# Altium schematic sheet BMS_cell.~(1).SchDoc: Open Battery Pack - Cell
size A4; Date: 26/03/2019; Author: Morgane Vallée - Samuel Lesueur; Revision: 1.0; SheetNumber: 3; SheetTotal: 3
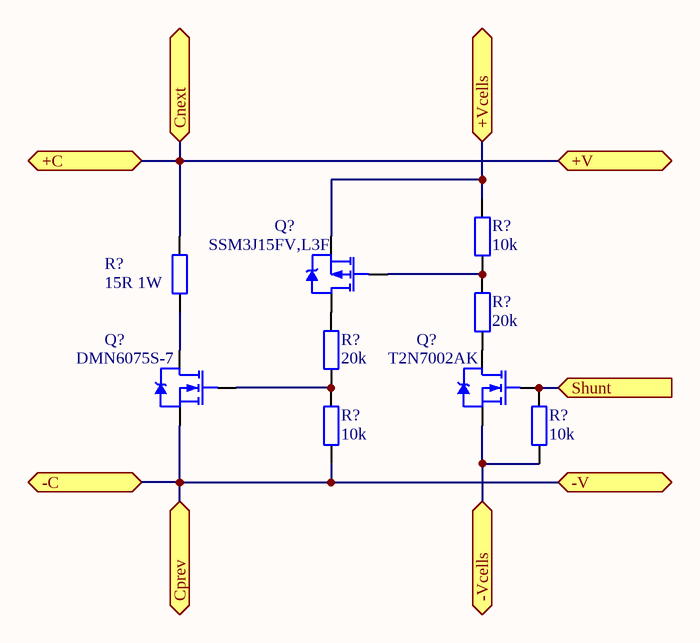
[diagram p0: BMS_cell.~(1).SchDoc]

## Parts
(Parts that share a designator on the sheet are numbered #1, #2 ... from top to bottom, then left to right.)
Q?#1  SSM3J15FV,L3F  [DIODES SOT-23-3]
Q?#2  DMN6075S-7  [DIODES SOT-23-3]
Q?#3  T2N7002AK  [DIODES SOT-23-3]
R?#1  10k  [R0603]
R?#2  15R 1W  [STACKPOLE CSR2512]
R?#3  20k  [R0603]
R?#4  20k  [R0603]
R?#5  10k  [R0603]
R?#6  10k  [R0603]

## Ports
+C, +V, +Vcells, -C, -V, -Vcells, Cnext, Cprev, Shunt (in)

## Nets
+C: R?#2.2 ; port +C, port Cnext, port +V
+Vcells: Q?#1.2(S) R?#1.2 ; port +Vcells
-C: Q?#2.2(S) R?#5.1 ; port -C, port Cprev, port -V
-Vcells: Q?#3.2(S) R?#6.1 ; port -Vcells
Shunt: Q?#3.1(G) R?#6.2 ; port Shunt
NetQ?#1_1: Q?#1.1(G) R?#1.1 R?#3.2
NetQ?#1_3: Q?#1.3(D) R?#4.2
NetQ?#2_1: Q?#2.1(G) R?#4.1 R?#5.2
NetQ?#2_3: Q?#2.3(D) R?#2.1
NetQ?#3_3: Q?#3.3(D) R?#3.1

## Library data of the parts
Q?#1 = MOSFET_P
Q?#2 Q?#3 = MOSFET_N
R?#1-R?#6 = Res2: Resistor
